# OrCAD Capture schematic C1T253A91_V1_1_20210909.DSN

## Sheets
1 05_SLAVE3_TLSR9: size A4; title: TELINK; rev: V1.1; note: C1T253A91_V1_1_20210909
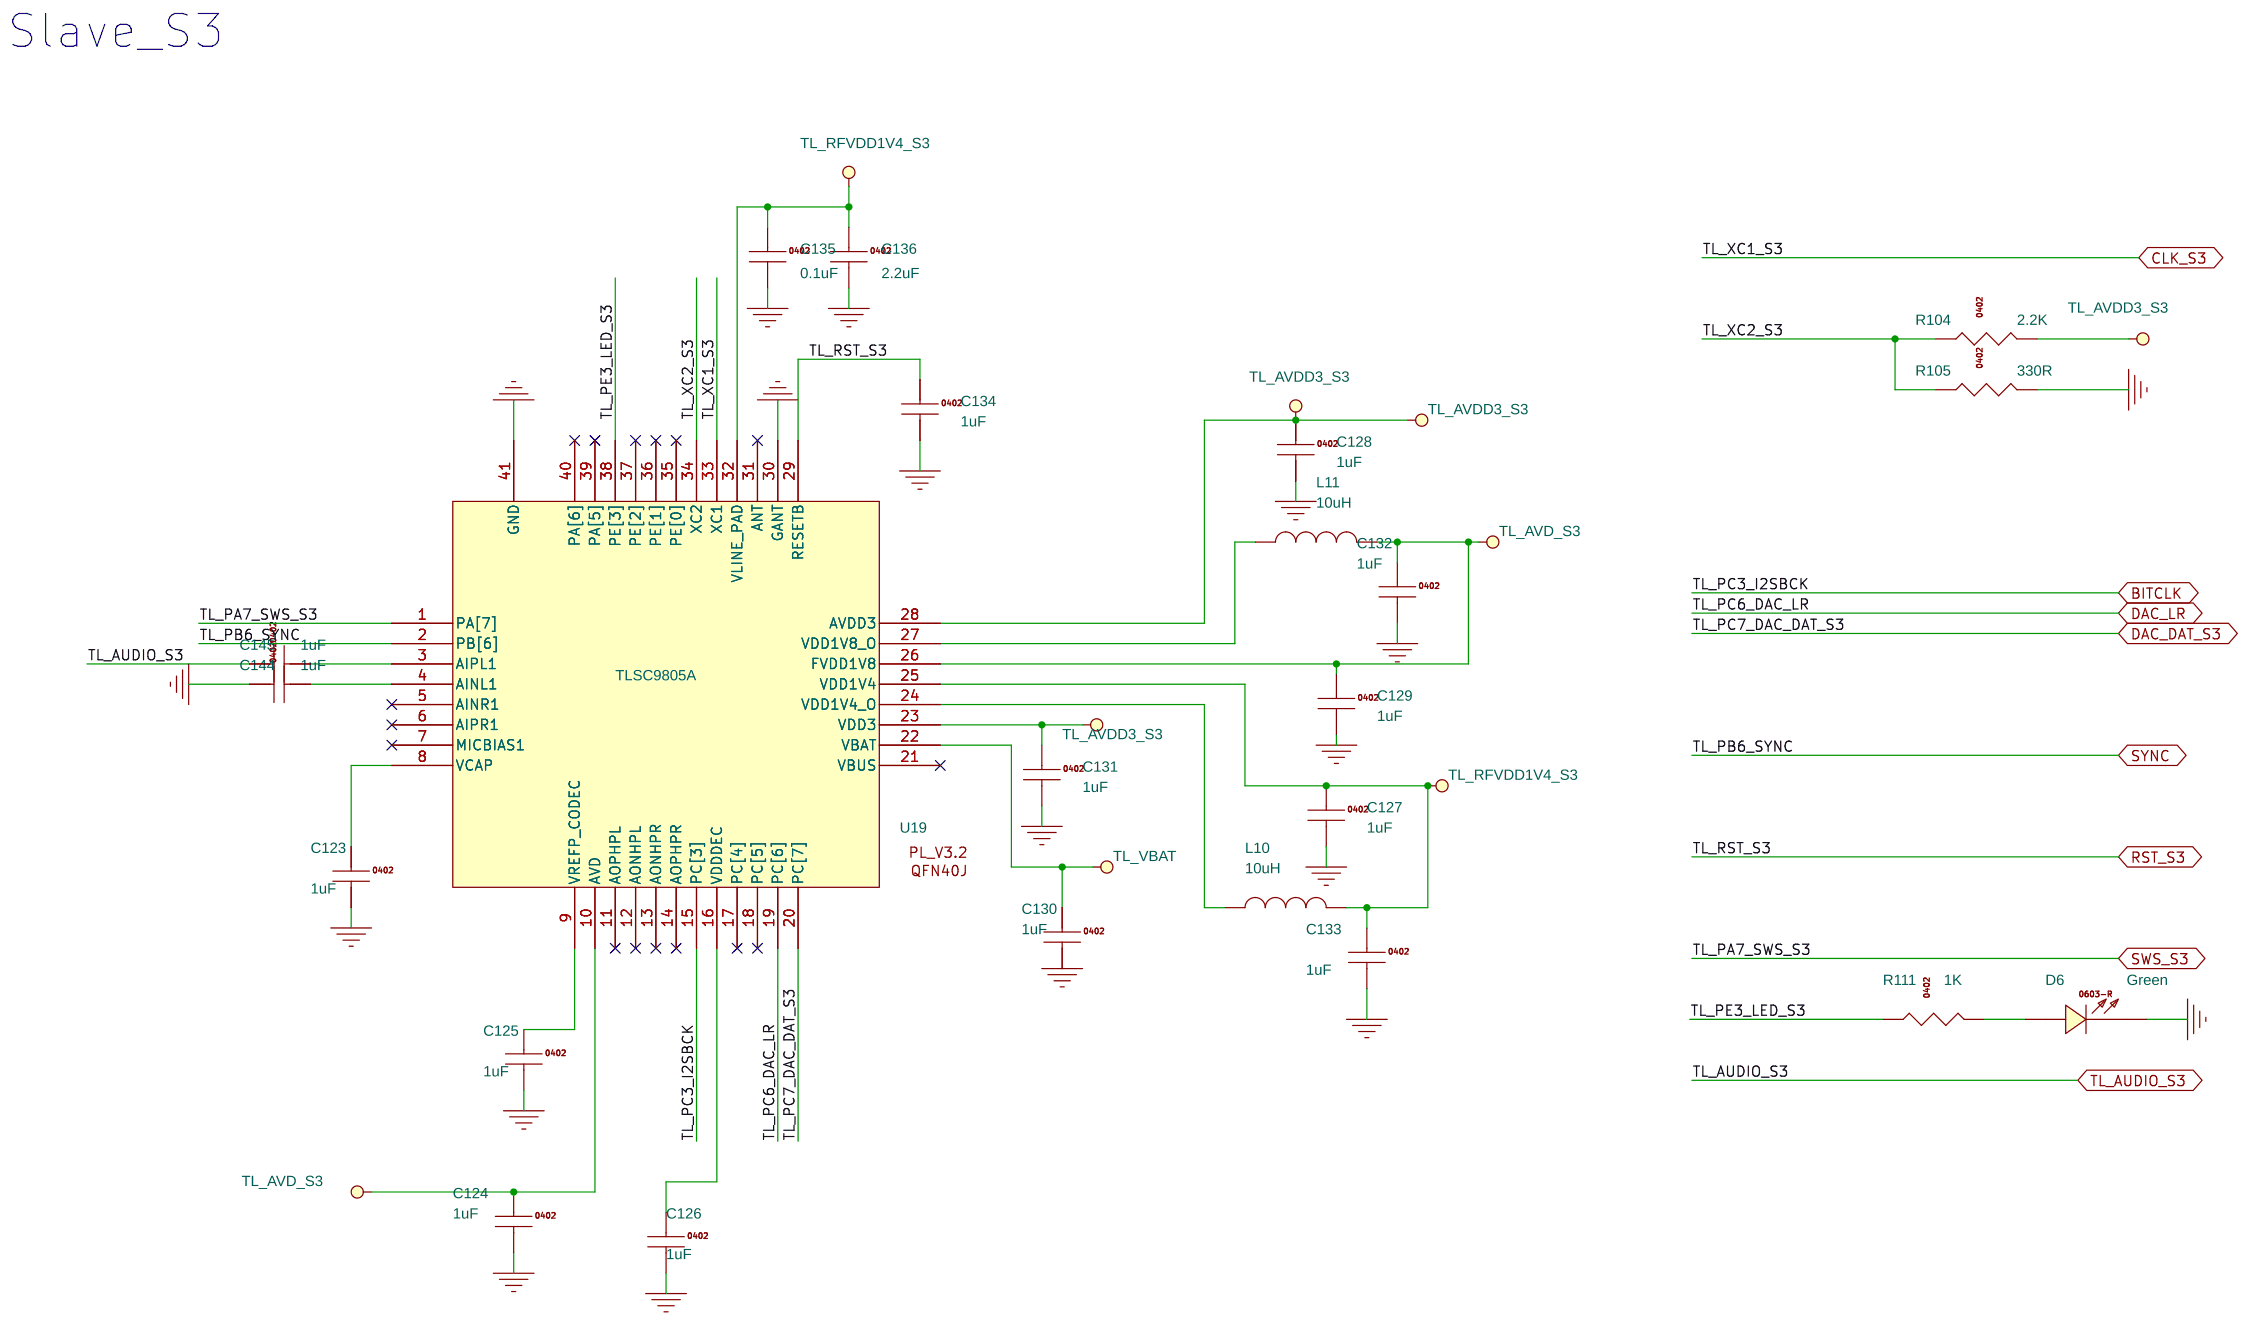
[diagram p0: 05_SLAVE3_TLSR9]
2 00_SOLUTION: rev: 1.1
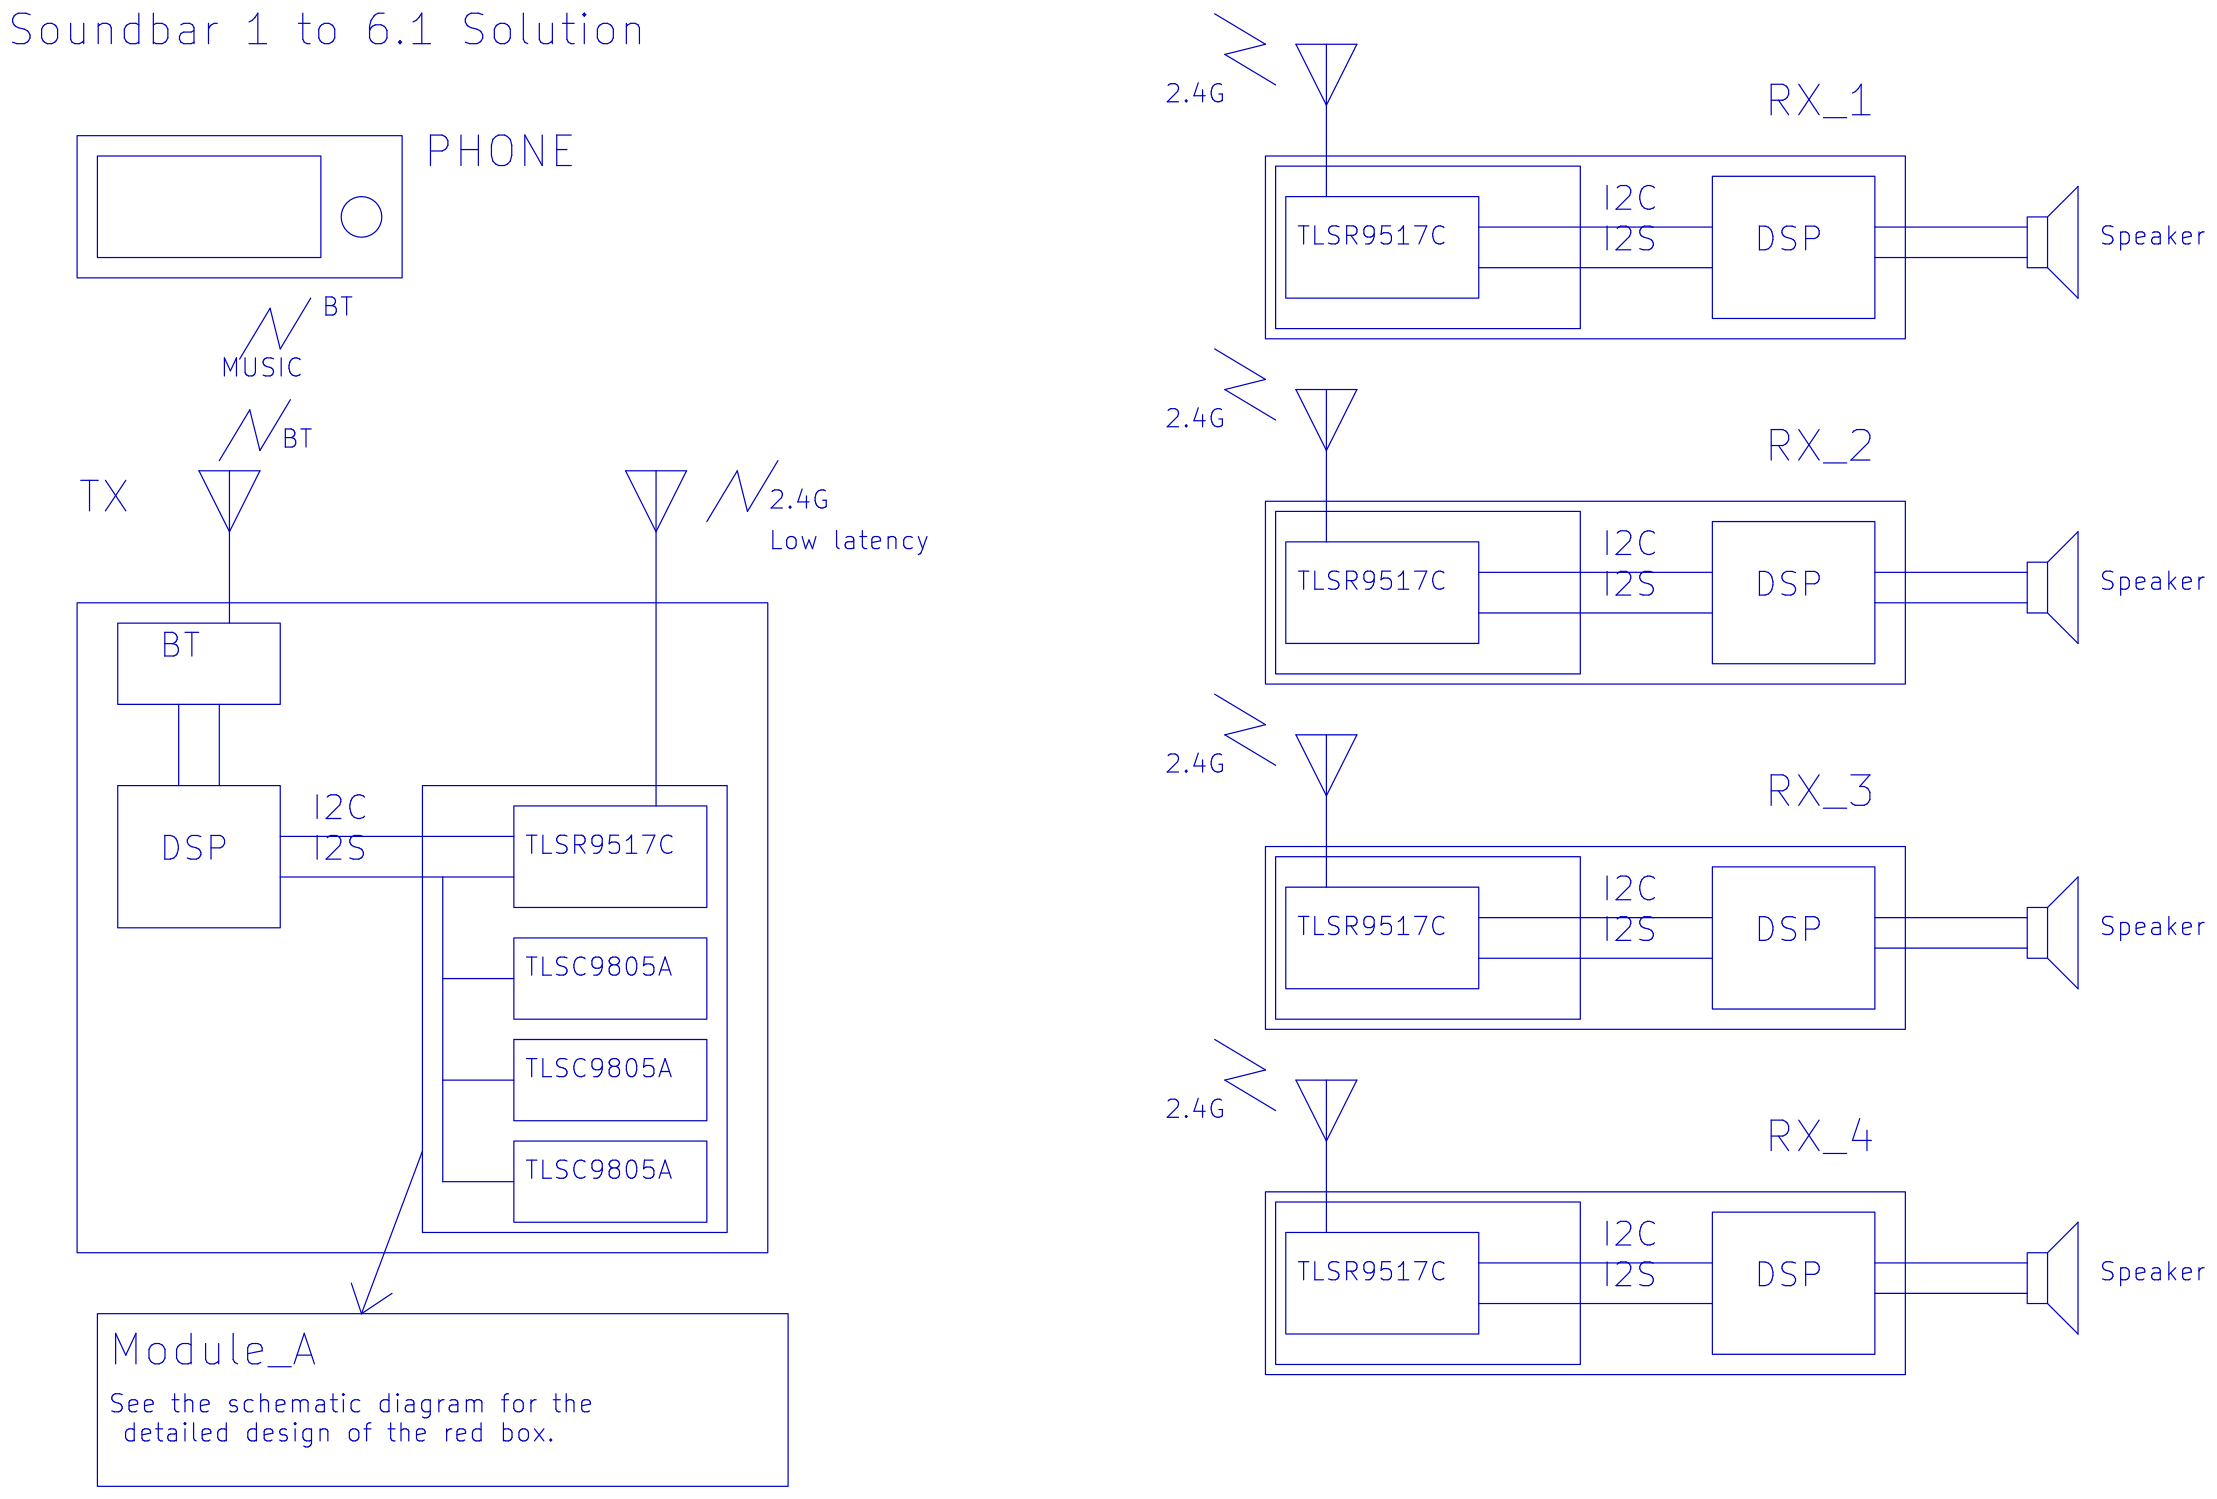
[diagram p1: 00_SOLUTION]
3 01_STR
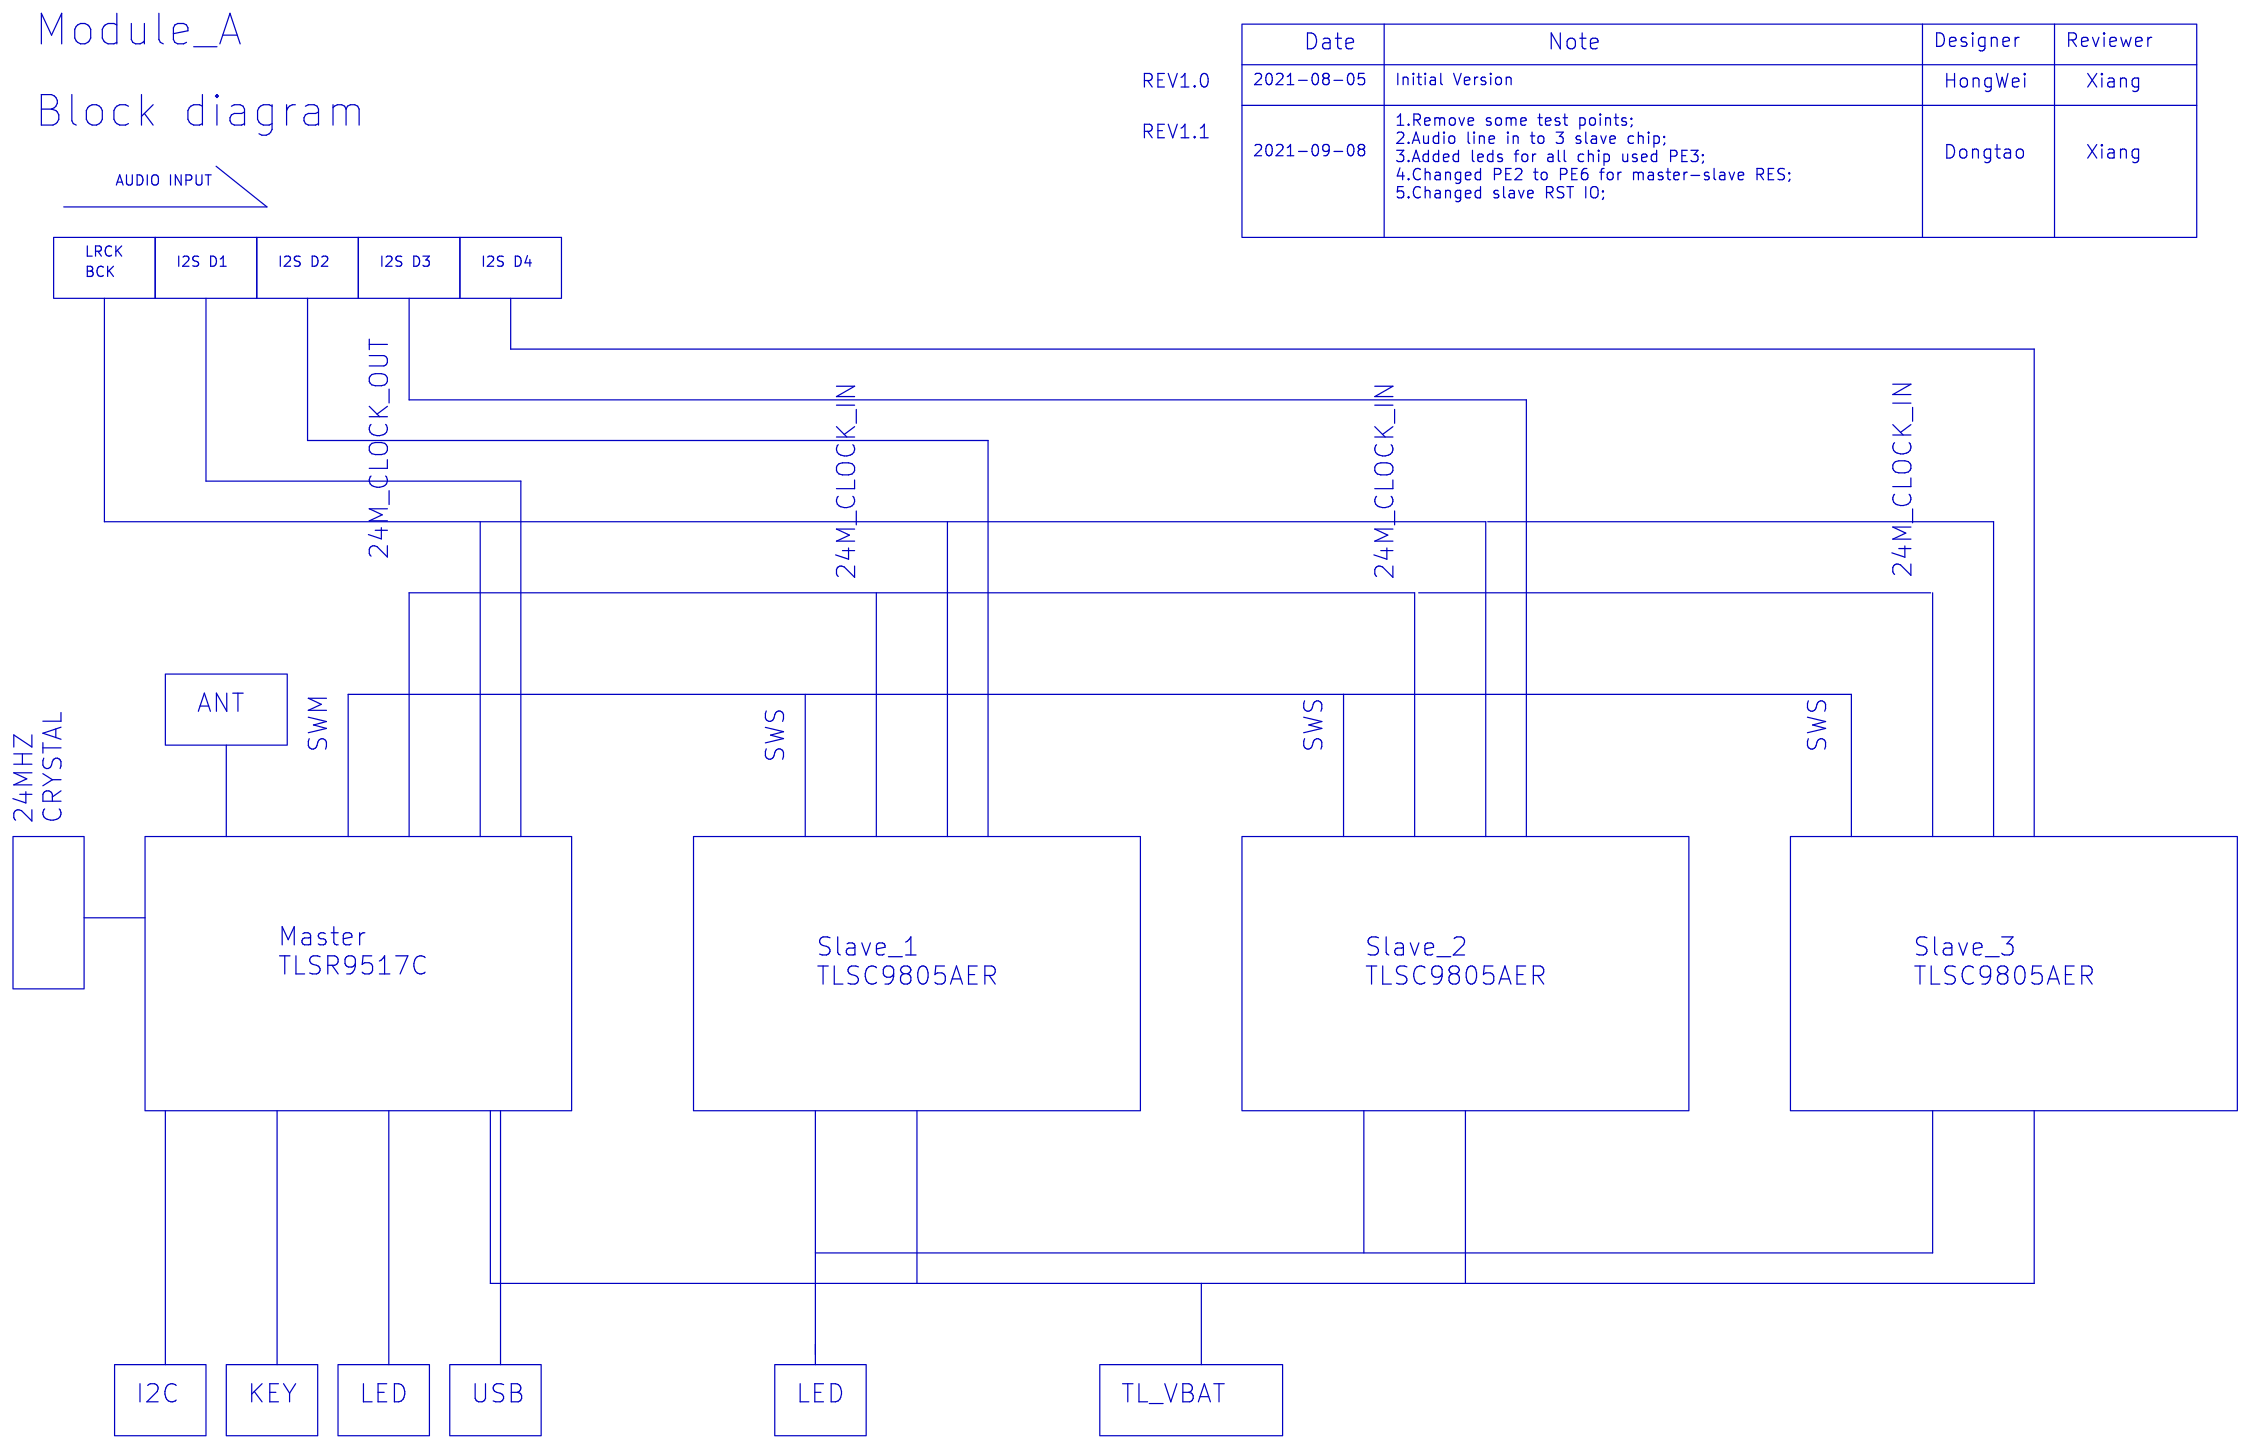
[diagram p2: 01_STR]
4 02_MASTER_TLSR9: size A3
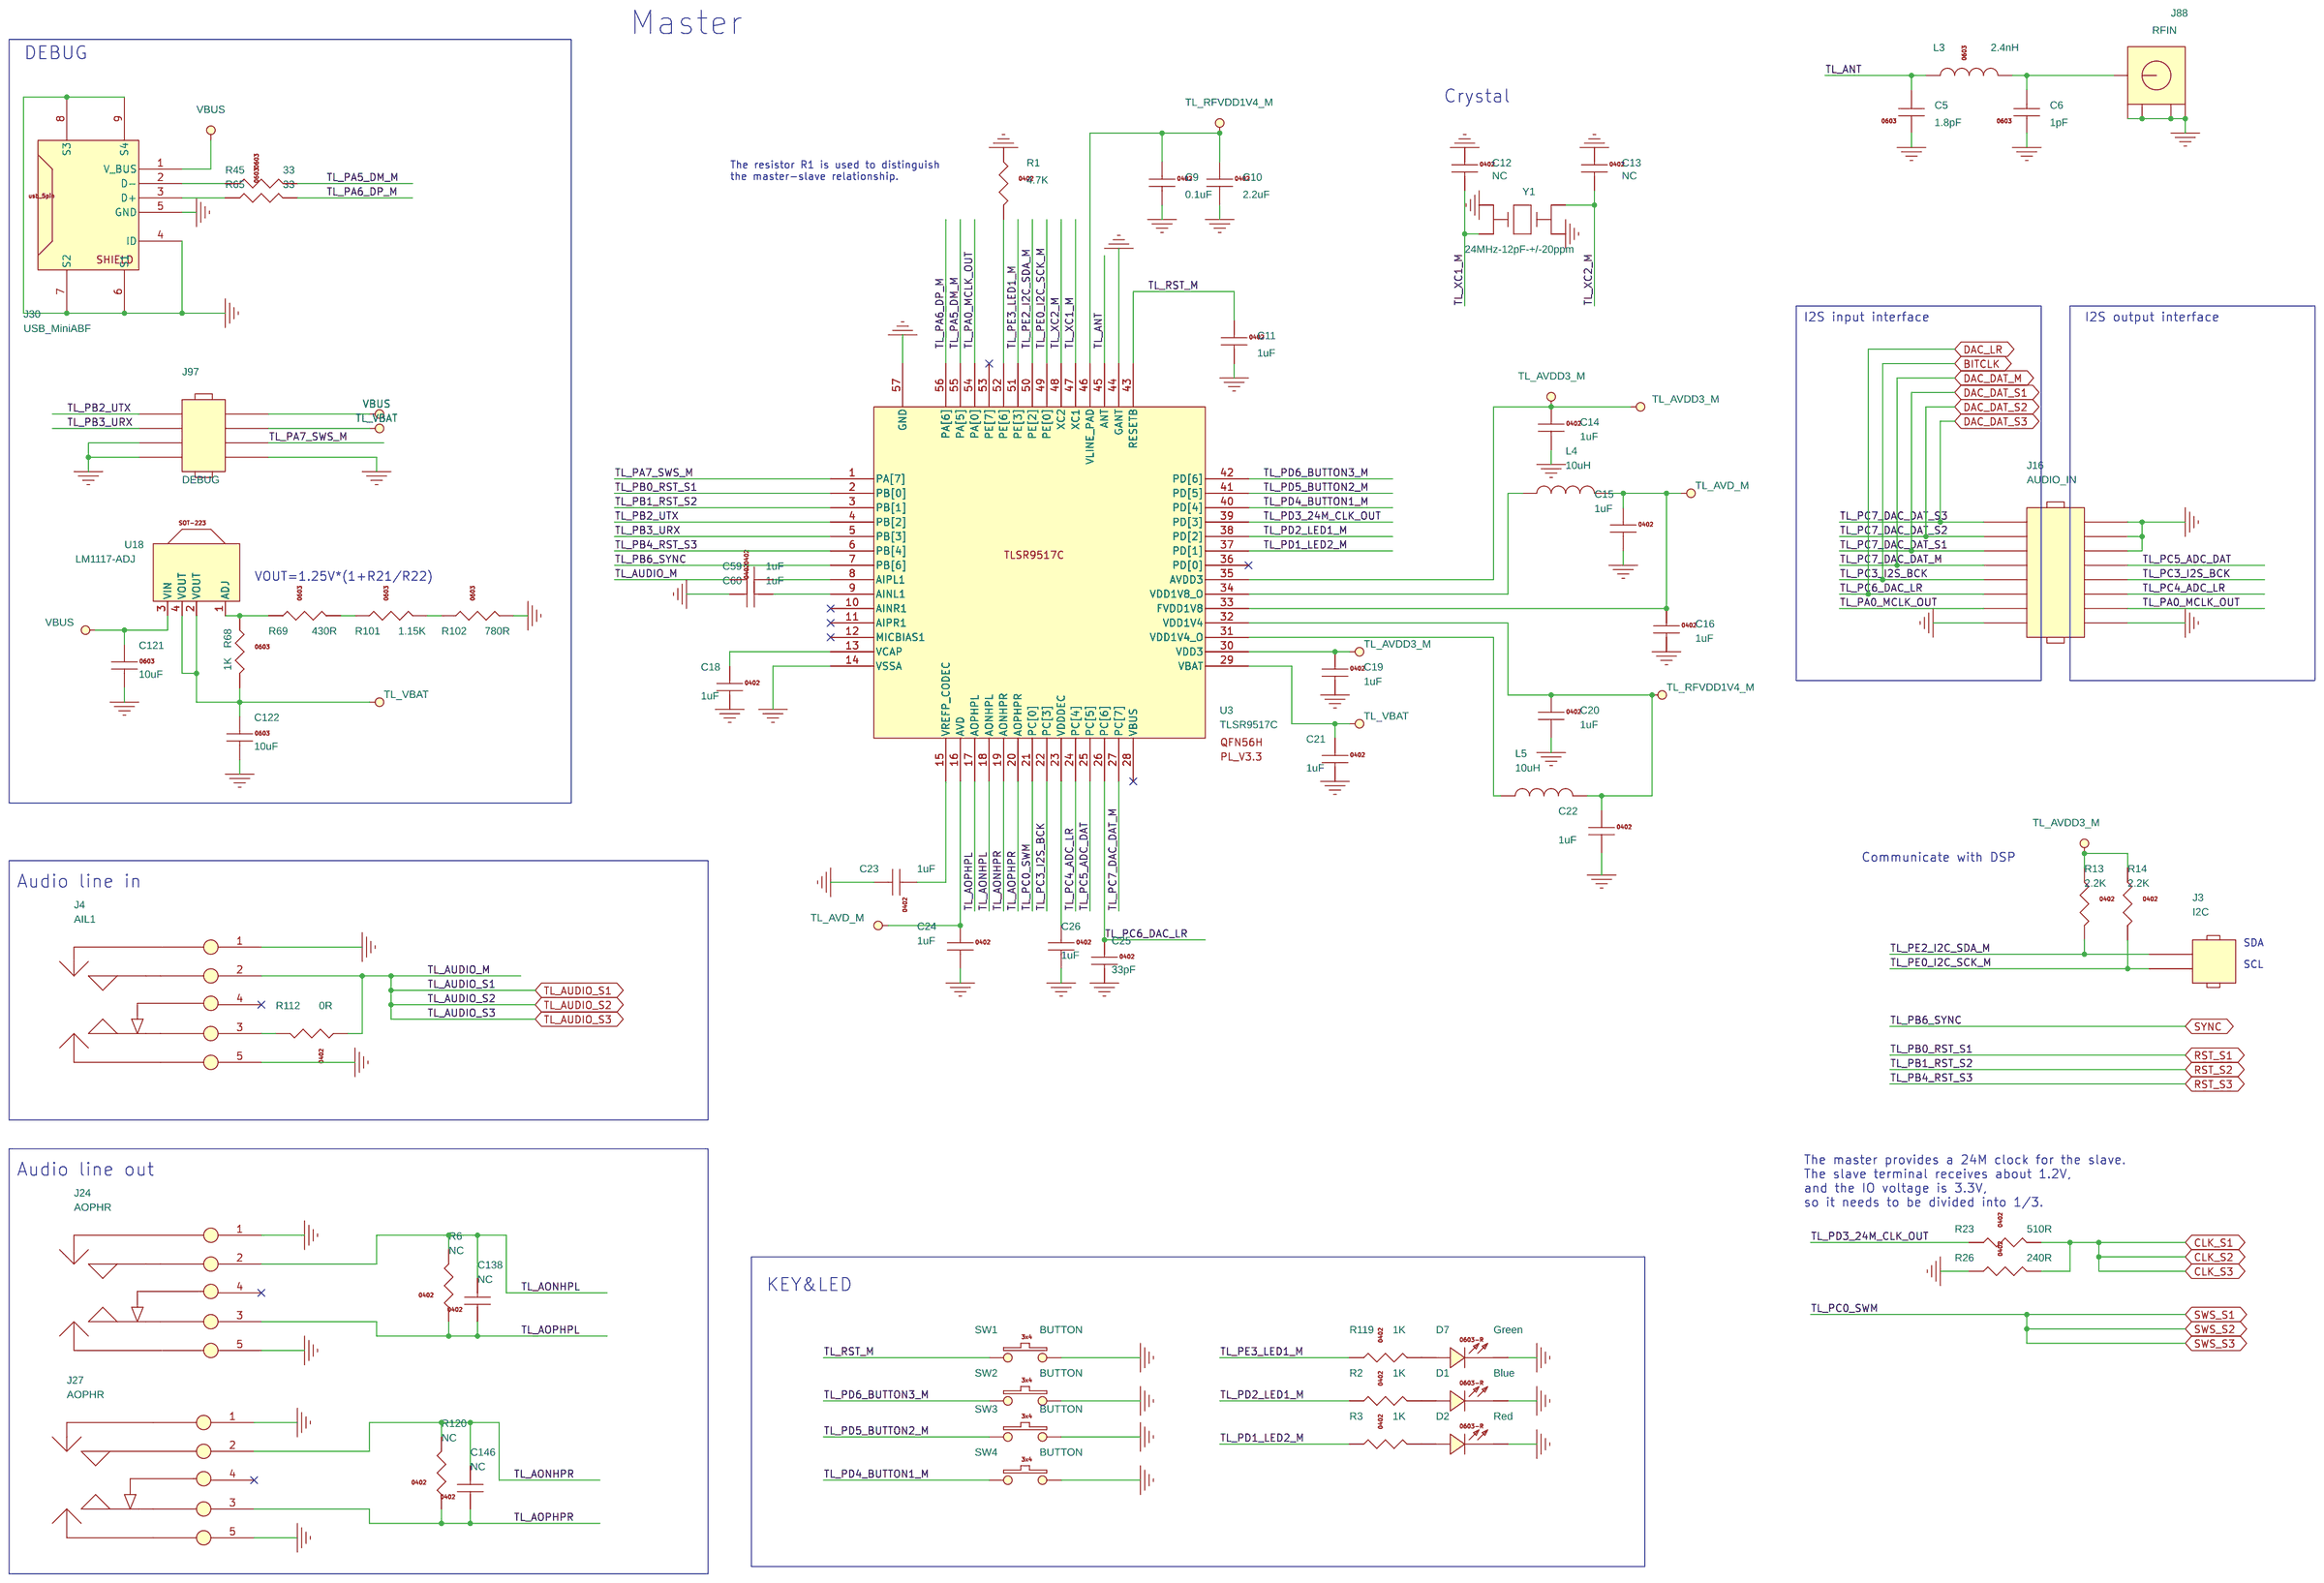
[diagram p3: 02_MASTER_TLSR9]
5 03_SLAVE1_TLSR9: size A4
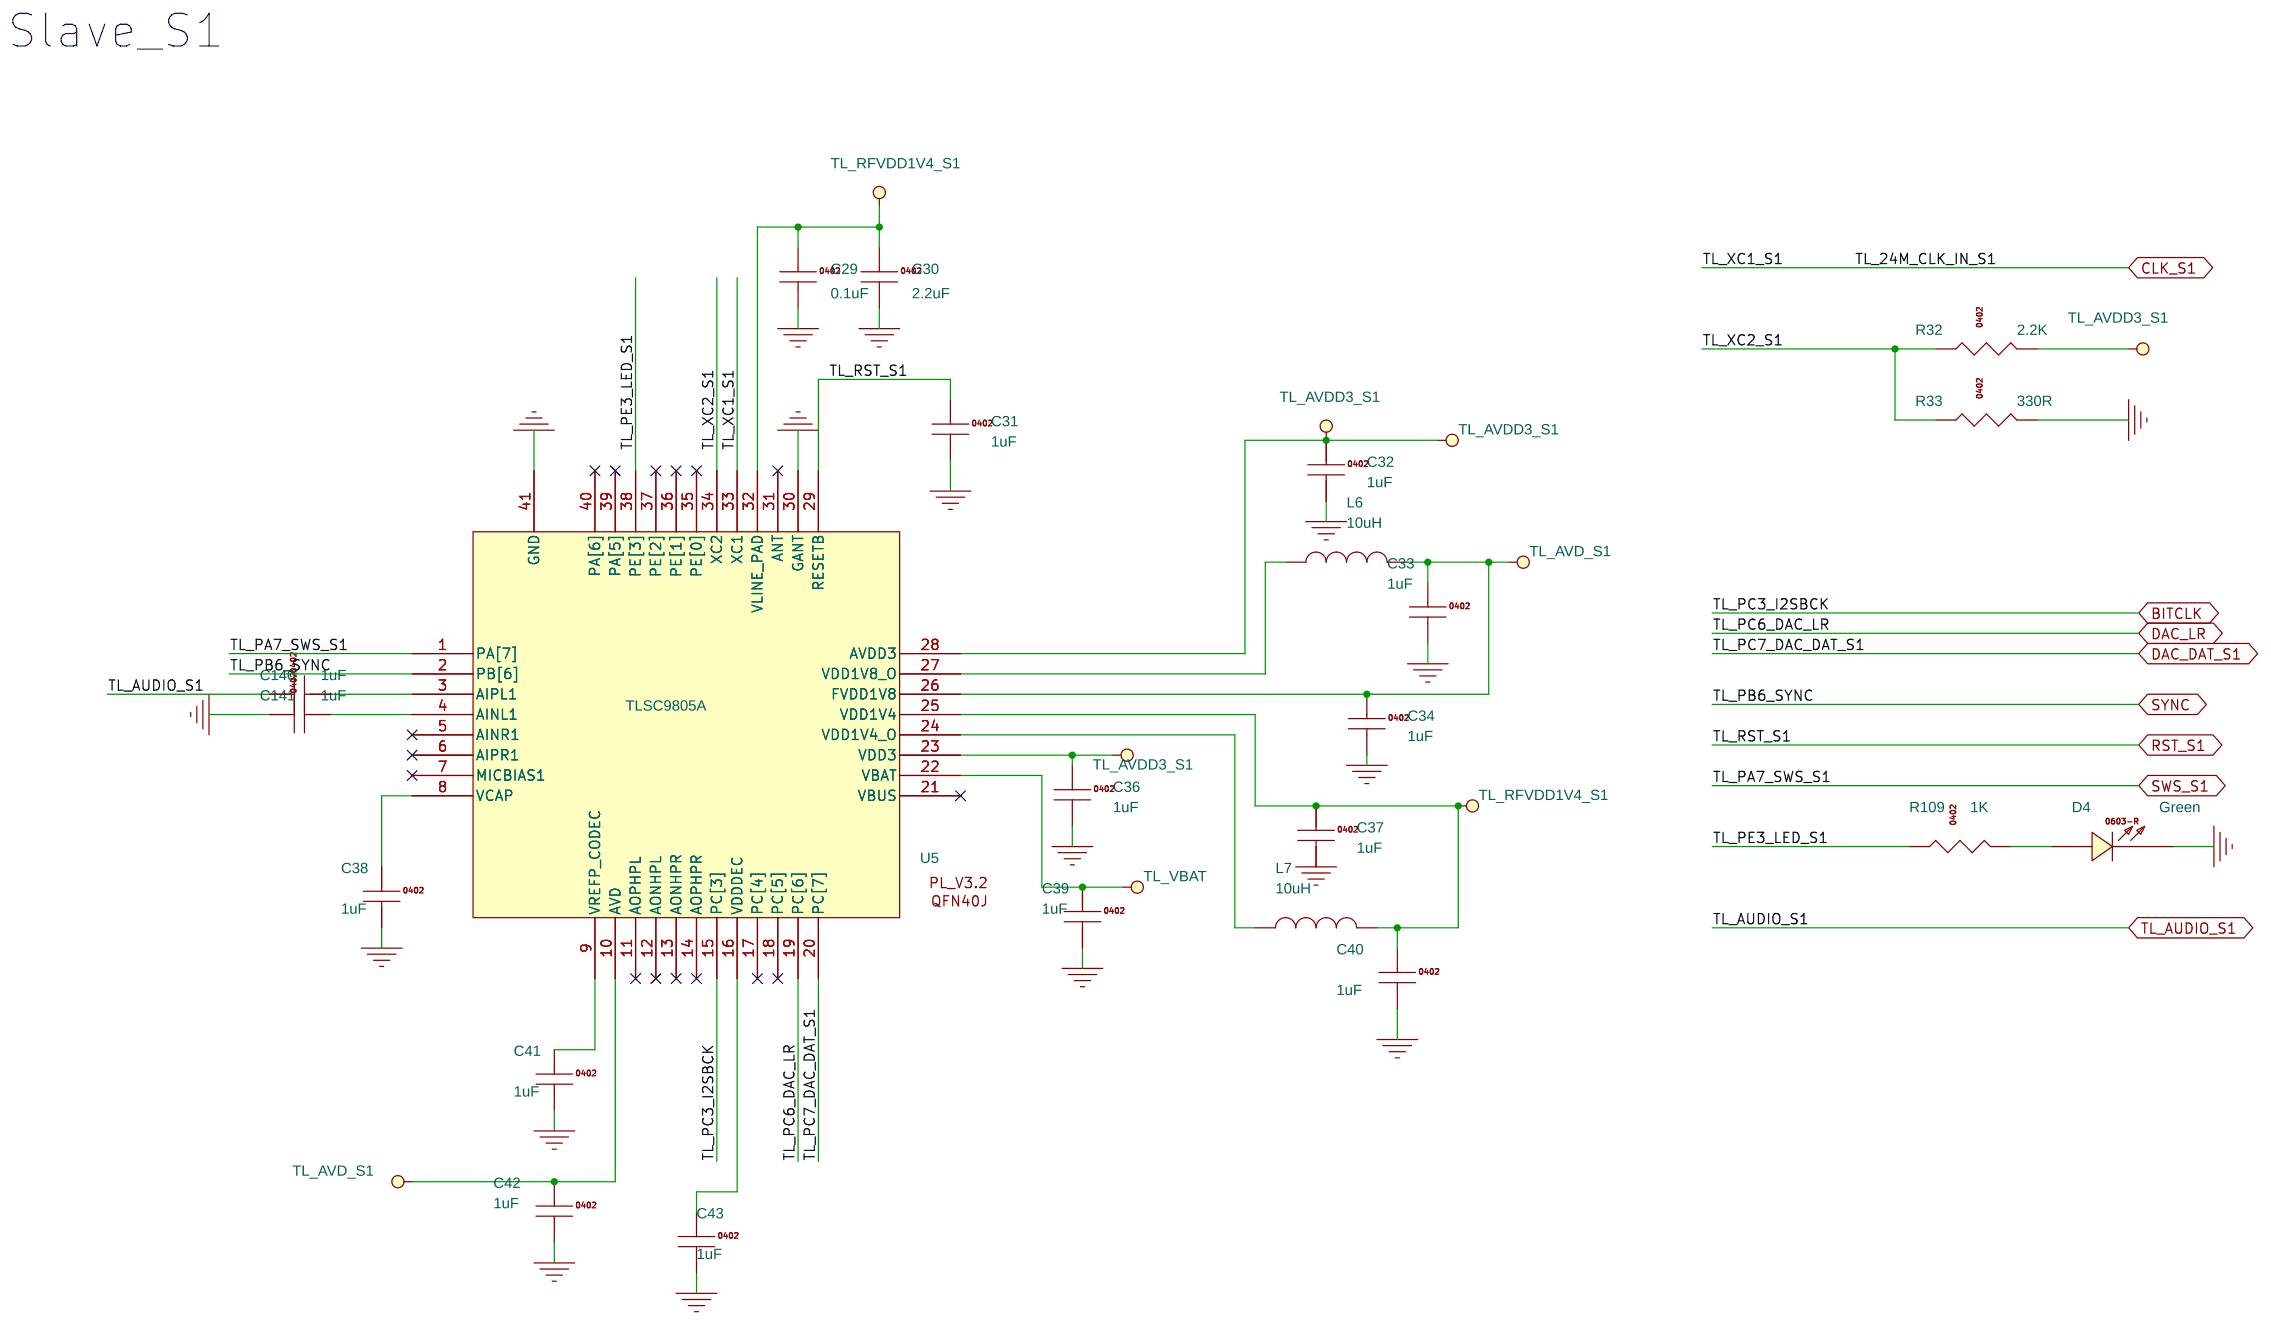
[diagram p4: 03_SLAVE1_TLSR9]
6 04_SLAVE2_TLSR9: size A4
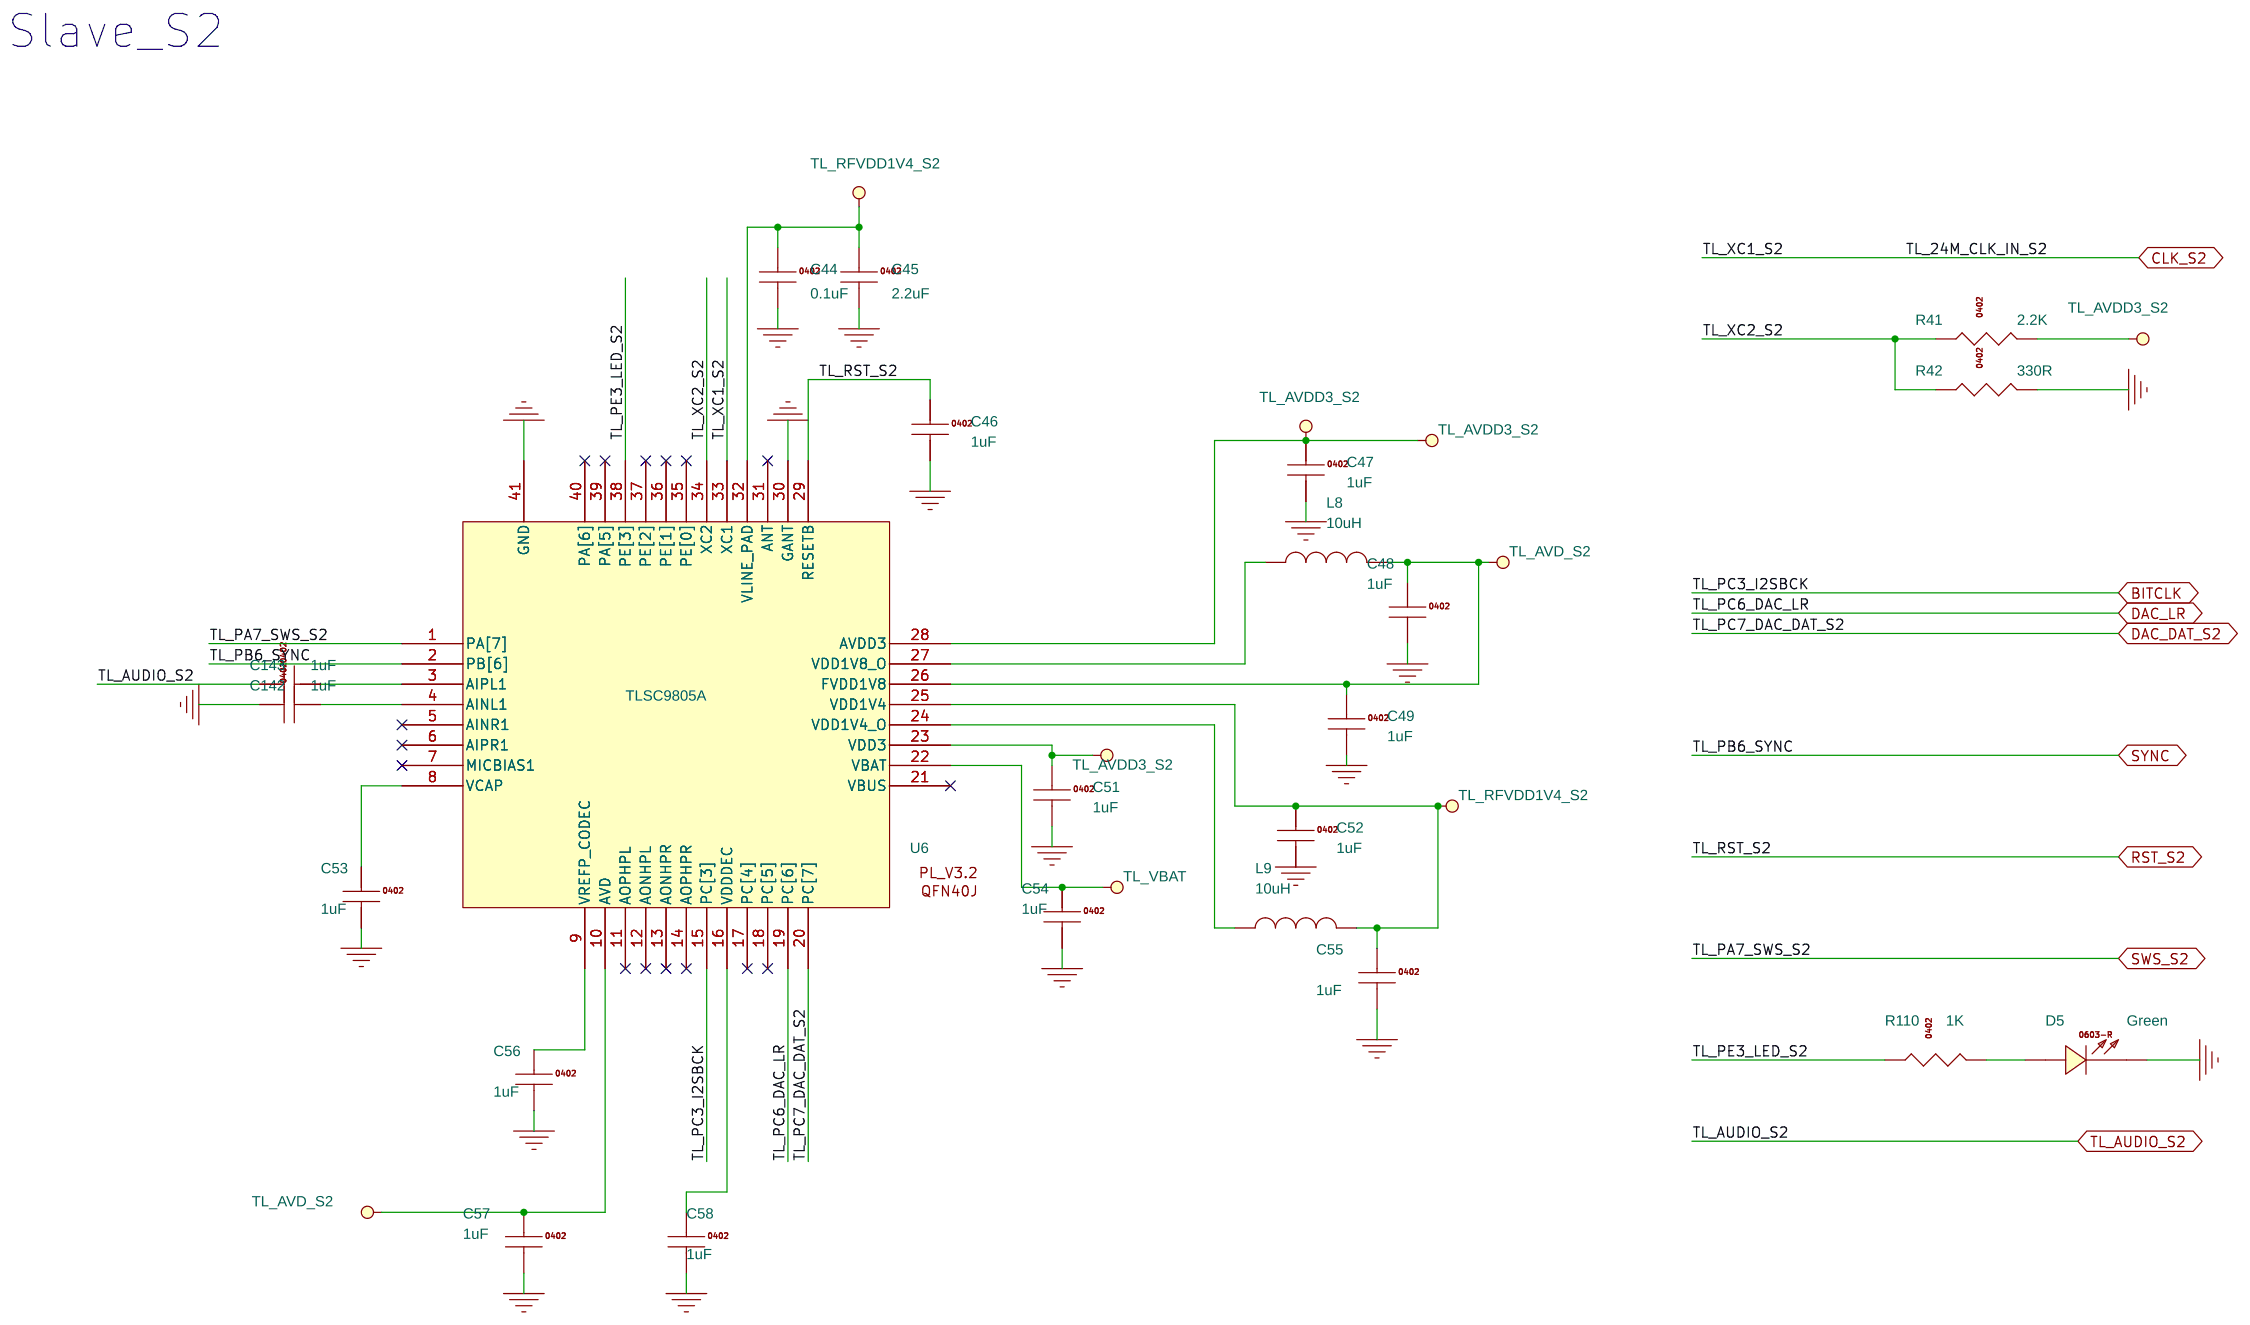
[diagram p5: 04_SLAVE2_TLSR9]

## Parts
sheet 02_MASTER_TLSR9
C5  1.8pF  [0402]
C6  1pF  [0402]
C9  0.1uF  [0402]
C10  2.2uF  [0402]
C11  1uF  [0402]
C12  NC  [0402]
C13  NC  [0402]
C14  1uF  [0402]
C15  1uF  [0402]
C16  1uF  [0402]
C18  1uF  [0402]
C19  1uF  [0402]
C20  1uF  [0402]
C21  1uF  [0402]
C22  1uF  [0402]
C23  1uF  [0402]
C24  1uF  [0402]
C25  33pF  [0402]
C26  1uF  [0402]
C59  1uF  [0402]
C60  1uF  [0402]
C121  10uF  [0603c]
C122  10uF  [0603C]
C138  NC  [0402]
C146  NC  [0402]
D1  Blue  [0603-LED]
D2  Red  [0603-LED]
D7  Green  [0603-LED]
J3  I2C  [HDR254F-1X2X850]
J4  AIL1  [PJ-327]
J16  AUDIO_IN  [hdr254f-2x8x850]
J24  AOPHR  [PJ-327]
J27  AOPHR  [PJ-327]
J30  USB_MiniABF  [usb-mini-f5]
J88  RFIN  [SMA-H]
J97  DEBUG  [hdr254f-2x4x850]
L3  2.4nH  [0402]
L4  10uH  [0805L]
L5  10uH  [0805L]
R1  4.7K  [0402]
R2  1K  [0402]
R3  1K  [0402]
R6  NC  [0402]
R13  2.2K  [0402]
R14  2.2K  [0402]
R23  510R  [0402]
R26  240R  [0402]
R45  33  [0402]
R65  33  [0402]
R68  1K  [0402]
R69  430R  [0402]
R101  1.15K  [0402]
R102  780R  [0402]
R112  0R  [0402]
R119  1K  [0402]
R120  NC  [0402]
SW1  BUTTON  [butsmd2px4_00y3_00_nh]
SW2  BUTTON  [butsmd2px4_00y3_00_nh]
SW3  BUTTON  [butsmd2px4_00y3_00_nh]
SW4  BUTTON  [butsmd2px4_00y3_00_nh]
U3  TLSR9517C  [qfn_7x7_56pin_0p4_4p10x4p10]
U18  LM1117-ADJ  [sot-223]
Y1  24MHz-12pF-+/-20ppm  [OSCCC250X320X110]
sheet 03_SLAVE1_TLSR9
C29  0.1uF  [0402]
C30  2.2uF  [0402]
C31  1uF  [0402]
C32  1uF  [0402]
C33  1uF  [0402]
C34  1uF  [0402]
C36  1uF  [0402]
C37  1uF  [0402]
C38  1uF  [0402]
C39  1uF  [0402]
C40  1uF  [0402]
C41  1uF  [0402]
C42  1uF  [0402]
C43  1uF  [0402]
C140  1uF  [0402]
C141  1uF  [0402]
D4  Green  [0603-LED]
L6  10uH  [0805L]
L7  10uH  [0805L]
R32  2.2K  [0402]
R33  330R  [0402]
R109  1K  [0402]
U5  TLSC9805A  [qfn_4x6_40pin_0p4_1p10x3p10]
sheet 04_SLAVE2_TLSR9
C44  0.1uF  [0402]
C45  2.2uF  [0402]
C46  1uF  [0402]
C47  1uF  [0402]
C48  1uF  [0402]
C49  1uF  [0402]
C51  1uF  [0402]
C52  1uF  [0402]
C53  1uF  [0402]
C54  1uF  [0402]
C55  1uF  [0402]
C56  1uF  [0402]
C57  1uF  [0402]
C58  1uF  [0402]
C142  1uF  [0402]
C143  1uF  [0402]
D5  Green  [0603-LED]
L8  10uH  [0805L]
L9  10uH  [0805L]
R41  2.2K  [0402]
R42  330R  [0402]
R110  1K  [0402]
U6  TLSC9805A  [qfn_4x6_40pin_0p4_1p10x3p10]
sheet 05_SLAVE3_TLSR9
C123  1uF  [0402]
C124  1uF  [0402]
C125  1uF  [0402]
C126  1uF  [0402]
C127  1uF  [0402]
C128  1uF  [0402]
C129  1uF  [0402]
C130  1uF  [0402]
C131  1uF  [0402]
C132  1uF  [0402]
C133  1uF  [0402]
C134  1uF  [0402]
C135  0.1uF  [0402]
C136  2.2uF  [0402]
C144  1uF  [0402]
C145  1uF  [0402]
D6  Green  [0603-LED]
L10  10uH  [0805L]
L11  10uH  [0805L]
R104  2.2K  [0402]
R105  330R  [0402]
R111  1K  [0402]
U19  TLSC9805A  [qfn_4x6_40pin_0p4_1p10x3p10]

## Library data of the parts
C5 C6 = C1608_NC
C9-C11 C14-C16 C18-C26 C29-C34 C36-C49 C51-C60 C123-C136 C140-C145 = C1005X5R1C104K
C12 C13 = C1005_NC
C121 = C1608X5R0J106M
C122 = C1608X5R1C105M
C138 C146 = C1005X5R1C105K
D1 D2 D4-D7 = 0603D_Red
J3 = HEADER_2
J4 J24 J27 = PJ327_2
J16 = HEADER_8X2
J30 = USB_MiniABF_5pin
J88 = SMA_JACK_2: PART: RF
J97 = HEADER_4X2
L3 = MLK1608_000R
L4-L11 = IND
R1 R6 R13 R14 R23 R26 R32 R33 R41 R42 R104 R105 R112 R120 = RS0402K104JT
R2 R3 R109-R111 R119 = RS0402K332JT
R45 R65 = RS0603K330JT
R68 R69 R101 R102 = RS0603K104JT
SW1-SW4 = SW2PIN_3x4
U3 = TLSR9517C_1
U18 = XC62FP3302_0.3V_SOT-89
Y1 = CRYSTAL4_SM_0
U5 U6 U19 = TLSC9805A_0

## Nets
GND: C5.1 C6.1 C9.2 C10.2 C11.2 C12.1 C13.1 C14.2 C15.2 C16.2 C18.2 C19.2 C20.2 C21.2 C22.2 C23.2 C24.2 C25.2 C26.2 C29.2 C30.2 C31.2 C32.2 C33.2 C34.2 C36.2 C37.2 C38.2 C39.2 C40.2 C41.2 C42.2 C43.2 C44.2 C45.2 C46.2 C47.2 C48.2 C49.2 C51.2 C52.2 C53.2 C54.2 C55.2 C56.2 C57.2 C58.2 C60.1 C121.2 C122.2 C123.2 C124.2 C125.2 C126.2 C127.2 C128.2 C129.2 C130.2 C131.2 C132.2 C133.2 C134.2 C135.2 C136.2 C141.1 C142.1 C144.1 D1.C(CATHODE) D2.C(CATHODE) D4.C(CATHODE) D5.C(CATHODE) D6.C(CATHODE) D7.C(CATHODE) J4.1 J4.5 J16.1 J16.3 J16.5 J16.15 J16.16 J24.1 J24.5 J27.1 J27.5 J30.4(ID) J30.5(GND) J30.6(S1) J30.7(S2) J30.8(S3) J30.9(S4) J88.2 J88.3 J88.4 J88.5 J97.6 J97.7 J97.8 R1.1 R26.1 R33.2 R42.2 R102.2 R105.2 SW1.2 SW2.2 SW3.2 SW4.2 U3.14(VSSA) U3.44(GANT) U3.57(GND) U5.30(GANT) U5.41(GND) U6.30(GANT) U6.41(GND) U19.30(GANT) U19.41(GND) Y1.2 Y1.4
VBUS: C121.1 J30.1(V_BUS) J97.1 U18.3(VIN)
BITCLK: J16.9 J16.10 U3.22(PC[3]) U5.15(PC[3]) U6.15(PC[3]) U19.15(PC[3])
CLK_S1: R23.2 R26.2 U5.33(XC1) U6.33(XC1) U19.33(XC1)
DAC_DAT_M: J16.8 U3.27(PC[7])
DAC_DAT_S1: J16.6 U5.20(PC[7])
DAC_DAT_S2: J16.4 U6.20(PC[7])
DAC_DAT_S3: J16.2 U19.20(PC[7])
DAC_LR: C25.1 J16.12 U3.26(PC[6]) U5.19(PC[6]) U6.19(PC[6]) U19.19(PC[6])
RST_S1: C31.1 U3.2(PB[0]) U5.29(RESETB)
RST_S2: C46.1 U3.3(PB[1]) U6.29(RESETB)
RST_S3: C134.1 U3.6(PB[4]) U19.29(RESETB)
SWS_S1: U3.21(PC[0]) U5.1(PA[7]) U6.1(PA[7]) U19.1(PA[7])
SYNC: U3.7(PB[6]) U5.2(PB[6]) U6.2(PB[6]) U19.2(PB[6])
TL_ANT: C5.2 L3.1 U3.45(ANT)
TL_AONHPL: C138.2 J24.2 R6.2 U3.18(AONHPL)
TL_AONHPR: C146.2 J27.2 R120.2 U3.19(AONHPR)
TL_AOPHPL: C138.1 J24.3 R6.1 U3.17(AOPHPL)
TL_AOPHPR: C146.1 J27.3 R120.1 U3.20(AOPHPR)
TL_AUDIO_S1: C59.1 C140.1 C143.1 C145.1 J4.2 R112.1
TL_AVD_M: C15.1 C16.1 C24.1 L4.2 U3.16(AVD) U3.33(FVDD1V8)
TL_AVD_S1: C33.1 C34.1 C42.1 L6.2 U5.10(AVD) U5.26(FVDD1V8)
TL_AVD_S2: C48.1 C49.1 C57.1 L8.2 U6.10(AVD) U6.26(FVDD1V8)
TL_AVD_S3: C124.1 C129.1 C132.1 L11.2 U19.10(AVD) U19.26(FVDD1V8)
TL_AVDD3_M: C14.1 C19.1 R13.1 R14.1 U3.30(VDD3) U3.35(AVDD3)
TL_AVDD3_S1: C32.1 C36.1 R32.2 U5.23(VDD3) U5.28(AVDD3)
TL_AVDD3_S2: C47.1 C51.1 R41.2 U6.23(VDD3) U6.28(AVDD3)
TL_AVDD3_S3: C128.1 C131.1 R104.2 U19.23(VDD3) U19.28(AVDD3)
TL_PA0_MCLK_OUT: J16.13 J16.14 U3.54(PA[0])
TL_PA5_DM_M: R45.2 U3.55(PA[5])
TL_PA6_DP_M: R65.2 U3.56(PA[6])
TL_PA7_SWS_M: J97.5 U3.1(PA[7])
TL_PB2_UTX: J97.2 U3.4(PB[2])
TL_PB3_URX: J97.4 U3.5(PB[3])
TL_PC4_ADC_LR: J16.11 U3.24(PC[4])
TL_PC5_ADC_DAT: J16.7 U3.25(PC[5])
TL_PD1_LED2_M: R3.1 U3.37(PD[1])
TL_PD2_LED1_M: R2.1 U3.38(PD[2])
TL_PD3_24M_CLK_OUT: R23.1 U3.39(PD[3])
TL_PD4_BUTTON1_M: SW4.1 U3.40(PD[4])
TL_PD5_BUTTON2_M: SW3.1 U3.41(PD[5])
TL_PD6_BUTTON3_M: SW2.1 U3.42(PD[6])
TL_PE0_I2C_SCK_M: J3.1 R14.2 U3.49(PE[0])
TL_PE2_I2C_SDA_M: J3.2 R13.2 U3.50(PE[2])
TL_PE3_LED1_M: R119.1 U3.51(PE[3])
TL_PE3_LED_S1: R109.1 U5.38(PE[3])
TL_PE3_LED_S2: R110.1 U6.38(PE[3])
TL_PE3_LED_S3: R111.1 U19.38(PE[3])
TL_RFVDD1V4_M: C9.1 C10.1 C20.1 C22.1 L5.2 U3.32(VDD1V4) U3.46(VLINE_PAD)
TL_RFVDD1V4_S1: C29.1 C30.1 C37.1 C40.1 L7.2 U5.25(VDD1V4) U5.32(VLINE_PAD)
TL_RFVDD1V4_S2: C44.1 C45.1 C52.1 C55.1 L9.2 U6.25(VDD1V4) U6.32(VLINE_PAD)
TL_RFVDD1V4_S3: C127.1 C133.1 C135.1 C136.1 L10.2 U19.25(VDD1V4) U19.32(VLINE_PAD)
TL_RST_M: C11.1 SW1.1 U3.43(RESETB)
TL_VBAT: C21.1 C39.1 C54.1 C122.1 C130.1 J97.3 R68.2 U3.29(VBAT) U5.22(VBAT) U6.22(VBAT) U18.2(VOUT) U18.4(VOUT) U19.22(VBAT)
TL_XC1_M: C12.2 U3.47(XC1) Y1.3
TL_XC2_M: C13.2 U3.48(XC2) Y1.1
TL_XC2_S1: R32.1 R33.1 U5.34(XC2)
TL_XC2_S2: R41.1 R42.1 U6.34(XC2)
TL_XC2_S3: R104.1 R105.1 U19.34(XC2)
N20339251: C18.1 U3.13(VCAP)
N20339567: C23.1 U3.15(VREFP_CODEC)
N20339740: C26.1 U3.23(VDDDEC)
N20340124: L4.1 U3.34(VDD1V8_O)
N20340134: L5.1 U3.31(VDD1V4_O)
N20349172: C38.1 U5.8(VCAP)
N20349354: C41.1 U5.9(VREFP_CODEC)
N20350037: C43.1 U5.16(VDDDEC)
N20350580: L7.1 U5.24(VDD1V4_O)
N20350582: L6.1 U5.27(VDD1V8_O)
N20367658: C53.1 U6.8(VCAP)
N20367674: C56.1 U6.9(VREFP_CODEC)
N20367749: C58.1 U6.16(VDDDEC)
N20367829: L9.1 U6.24(VDD1V4_O)
N20367831: L8.1 U6.27(VDD1V8_O)
N20435584: C6.2 J88.1 L3.2
N20442183: C59.2 U3.8(AIPL1)
N20442186: C60.2 U3.9(AINL1)
N20446937: J30.3(D+) R65.1
N20446945: J30.2(D-) R45.1
N20447032: R69.2 R101.1
N20447038: R68.1 R69.1 U18.1(ADJ)
N20447058: R101.2 R102.1
N20449953: C123.1 U19.8(VCAP)
N20449969: C125.1 U19.9(VREFP_CODEC)
N20450013: C126.1 U19.16(VDDDEC)
N20450064: L11.1 U19.27(VDD1V8_O)
N20450066: L10.1 U19.24(VDD1V4_O)
N20490300: D4.A(ANODE) R109.2
N20490451: D5.A(ANODE) R110.2
N20490658: D6.A(ANODE) R111.2
N20496511: R1.2 U3.52(PE[6])
N20499472: C141.2 U5.4(AINL1)
N20499474: C140.2 U5.3(AIPL1)
N20499818: C142.2 U6.4(AINL1)
N20499820: C143.2 U6.3(AIPL1)
N20500173: C144.2 U19.4(AINL1)
N20500175: C145.2 U19.3(AIPL1)
N20500676: J4.3 R112.2
N20530695: D2.A(ANODE) R3.2
N20530696: D1.A(ANODE) R2.2
N20530700: D7.A(ANODE) R119.2

Not connected (* = marked no-connect by the designer): J4 4*; J24 4*; J27 4*; U3 10(AINR1)* 11(AIPR1)* 12(MICBIAS1)* 28(VBUS)* 36(PD[0])* 53(PE[7])*; U5 5(AINR1)* 6(AIPR1)* 7(MICBIAS1)* 11(AOPHPL)* 12(AONHPL)* 13(AONHPR)* 14(AOPHPR)* 17(PC[4])* 18(PC[5])* 21(VBUS)* 31(ANT)* 35(PE[0])* 36(PE[1])* 37(PE[2])* 39(PA[5])* 40(PA[6])*; U6 5(AINR1)* 6(AIPR1)* 7(MICBIAS1)* 11(AOPHPL)* 12(AONHPL)* 13(AONHPR)* 14(AOPHPR)* 17(PC[4])* 18(PC[5])* 21(VBUS)* 31(ANT)* 35(PE[0])* 36(PE[1])* 37(PE[2])* 39(PA[5])* 40(PA[6])*; U19 5(AINR1)* 6(AIPR1)* 7(MICBIAS1)* 11(AOPHPL)* 12(AONHPL)* 13(AONHPR)* 14(AOPHPR)* 17(PC[4])* 18(PC[5])* 21(VBUS)* 31(ANT)* 35(PE[0])* 36(PE[1])* 37(PE[2])* 39(PA[5])* 40(PA[6])*

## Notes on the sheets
sheet 1
- Slave_S3
sheet 2
- Soundbar 1 to 6.1 Solution
- 2.4G
- RX_1
- PHONE
- I2C
- TLSR9517C
- I2S
- DSP
- Speaker
- BT
- MUSIC
- BT
- 2.4G
- RX_2
- TX
- 2.4G
- Low latency
- I2C
- TLSR9517C
- I2S
- DSP
- Speaker
- BT
- 2.4G
- RX_3
- I2C
- DSP
- I2S
- TLSR9517C
- I2C
- TLSR9517C
- I2S
- DSP
- Speaker
- TLSC9805A
- TLSC9805A
- 2.4G
- RX_4
- TLSC9805A
- I2C
- TLSR9517C
- I2S
- DSP
- Speaker
- Module_A
- See the schematic diagram for the
   detailed design of the red box.
sheet 3
- Module_A
- Date
- Note
- Designer
- Reviewer
- REV1.0
- 2021-08-05
- Initial Version
- HongWei
- Xiang
- Block diagram
- REV1.1
- 1.Remove some test points;
  2.Audio line in to 3 slave chip;
  3.Added leds for all chip used PE3;
  4.Changed PE2 to PE6 for master-slave RES;
  5.Changed slave RST IO;
- 2021-09-08
- Dongtao
- Xiang
- AUDIO INPUT
- LRCK
- BCK
- I2S D1
- I2S D2
- I2S D3
- I2S D4
- 24M_CLOCK_OUT
- 24M_CLOCK_IN
- 24M_CLOCK_IN
- 24M_CLOCK_IN
- ANT
- SWM
- SWS
- SWS
- SWS
- 24MHZ
  CRYSTAL
- Master
  TLSR9517C
- Slave_1
  TLSC9805AER
- Slave_2
  TLSC9805AER
- Slave_3
  TLSC9805AER
- I2C
- KEY
- LED
- USB
- LED
- TL_VBAT
sheet 4
- Master
- DEBUG
- Crystal
- The resistor R1 is used to distinguish
  the master-slave relationship.
- I2S input interface
- I2S output interface
- VOUT=1.25V*(1+R21/R22)
- Communicate with DSP
- Audio line in
- SDA
- SCL
- Audio line out
- The master provides a 24M clock for the slave.
  The slave terminal receives about 1.2V,
  and the IO voltage is 3.3V,
  so it needs to be divided into 1/3.
- KEY&LED
sheet 5
- Slave_S1
sheet 6
- Slave_S2
